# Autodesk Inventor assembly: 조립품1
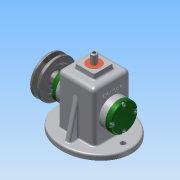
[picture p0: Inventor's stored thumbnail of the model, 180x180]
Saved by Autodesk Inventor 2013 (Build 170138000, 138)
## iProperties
Created: 2017-07
Part Number: 조립품1
Document SubType Name: Assembly
Designer: Administrator
Author: Administrator
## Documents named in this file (16)
- C:\Users\Administrator\Desktop\470708V1002\조립품1.iam
- C:\Users\Administrator\Desktop\470708V1002\본체.ipt
- C:\Users\Administrator\Desktop\470708V1002\슬라이드.ipt
- C:\Users\Administrator\Desktop\470708V1002\부시.ipt
- C:\Users\Administrator\Desktop\470708V1002\앞커버.ipt
- C:\Users\Administrator\Desktop\470708V1002\뒤커버.ipt
- C:\Users\Administrator\Desktop\470708V1002\베어링 12 x 32 x 10.ipt
- C:\Users\Administrator\Desktop\470708V1002\링크.ipt
- C:\Users\Administrator\Desktop\470708V1002\편심축.ipt
- C:\Users\Administrator\Desktop\470708V1002\핀 5 x 18.ipt
- C:\Users\Administrator\Desktop\470708V1002\키 4 x 4 x 10.ipt
- C:\Users\Administrator\Desktop\470708V1002\고정핀 1.2 x  8.ipt
- C:\Users\Administrator\Desktop\470708V1002\V벨트풀리.ipt
- C:\Users\Administrator\Desktop\470708V1002\오일실 12 25 7.ipt
- C:\Users\Administrator\Desktop\470708V1002\멈춤나사 M3x8.ipt
- C:\Users\Administrator\Desktop\470708V1002\볼트 M4 x 12.ipt
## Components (3 placed, 3 different names)
1. 핀 5 x 18:1
2. 고정핀 1.2 x  8:1
3. V벨트풀리:1 — 플러쉬:2
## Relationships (1: Flush 1)
- 플러쉬:2 [Flush]: V벨트풀리:1
